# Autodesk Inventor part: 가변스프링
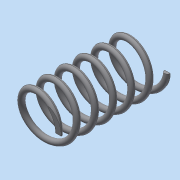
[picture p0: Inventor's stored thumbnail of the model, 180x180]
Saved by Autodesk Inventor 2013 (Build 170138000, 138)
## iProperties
Created: 2018-06
Part Number: 가변스프링
Material: 일반
Document SubType Name: Modeling
Designer: dgall
Density: 1 g/cm^3
Author: dgall
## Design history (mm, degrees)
sketch "스케치1"
  geometry: L1 (0, 0)-(0, 38); L2 (0, 38)-(8, 38); L3 (0, 0)-(8, 0); C1 r 1 at (8, 0)
  constraints: 6 end point, 2 parallel, 1 centre point, 1 coincident, 1 perpendicular, 1 vertical
  dimensions: "d0" = 38 distance of L1.start L1.end (derived); "d1" = 16 diameter of L2.end L1; "d2" = 1 radius of C1
feature "코일1" pitch "d3" = 10; turns "d5" = 6; dims "d4" = 37.99994 (computed from d0), "d6" = 0, angle "d7" = 90 deg, angle "d8" = 90 deg, "d9" = 0, "d10" = 0
feature "분할1"
node "작업 평면1"
feature "분할2"
node "솔리드1"
other parameters: "d11" = 0
